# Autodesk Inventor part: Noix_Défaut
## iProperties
Shininess: 64.0
Length Units: 11269
Angle Units: 11279
Time Units: 11290
Mass Units: 11283
Length Display Precision: 3
Angle Display Precision: 2
Compacted: True
Part Number: Noix_Défaut
Document SubType Name: Modeling
Created: 2006-01
Material: Par défaut
Designer: riri
Density: 0.0
Volumn: 0.0
Area: 0.0
PropertySet Name: Model Information
Control State: 0
Master: False
Checked Out: False
Author: riri
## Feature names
1. Base1
